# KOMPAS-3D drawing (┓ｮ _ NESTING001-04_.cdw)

Views: Вид 1, Снизу
Referenced files in \\Smallatom\скворечник\: Дно.m3d, Дно _ NESTING001-04.cdw
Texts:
  NESTING001-04
  Дно
  Лит-Масса-Масштаб
  Материал-Предприятие
  Title Specification
  Body Specification ( left align )
  Body Specificaton ( centered )
  Поз.
  Кол.
  Приме-
  чание
  Таблица спецификации
  Демьянова Л.В.
  NESTING001-04-
  КЮТ СО РАН
Dimensions and other numbers on the sheet: 120; 6; 1:2; 1; 0,25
